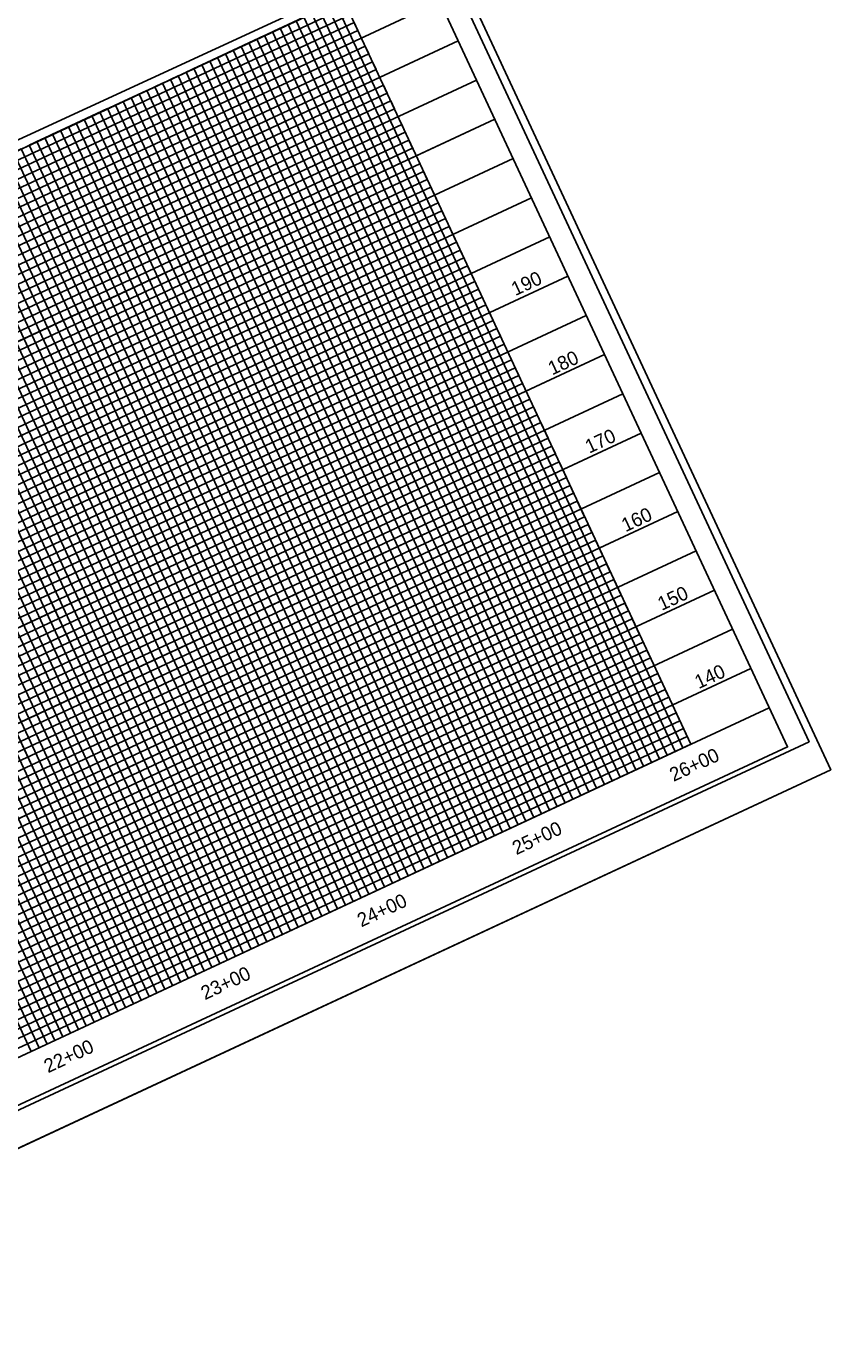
# Model space of a CAD drawing. Extents: x 2320593 to 2322597, y 921119 to 922832.
# Drawn here: x 2322132 to 2322597, y 921501 to 922260 of the extents above; entities that cross this region are included whole.
import ezdxf

# ---------------------------------------------------------------- set-up
doc = ezdxf.new("R2010")
doc.units = 0
for name, color, linetype in [('Default', 7, 'Continuous'), ('Sheet Cutting Line CELL', 7, 'Continuous'), ('Sheet DOT Grid CELL', 7, 'Continuous'), ('Sheet Layout Plan Border', 7, 'Continuous'), ('Sheet Layout Profile Border Port 2', 7, 'Continuous'), ('Sheet Plan And Profile CELL', 7, 'Continuous'), ('Sheet Plot Border Inside CELL', 7, 'Continuous'), ('Sheet Plot Border Outside CELL', 7, 'Continuous'), ('Sheet Profile Grid Major CELL', 7, 'Continuous'), ('Sheet Profile Grid Middle CELL', 7, 'Continuous'), ('Sheet Profile Grid Minor CELL', 7, 'Continuous')]:
    doc.layers.add(name, color=color, linetype=linetype)

msp = doc.modelspace()

# ---------------------------------------------------------------- linework, layer by layer
at = {"layer": 'Sheet Cutting Line CELL'}
msp.add_line((2321070.79, 921118.97), (2322596.67, 921830.22), dxfattribs=at)
at = {"layer": 'Sheet DOT Grid CELL'}
for p, q in [((2321000.96, 921662.89), (2322360.52, 922296.61)), ((2322315.2, 922275.49), (2322515.88, 921844.96)), ((2321022.08, 921617.57), (2322381.64, 922251.29)), ((2322269.88, 922254.36), (2322470.56, 921823.84)), ((2322224.56, 922233.24), (2322425.24, 921802.71)), ((2322179.24, 922212.12), (2322379.92, 921781.59)), ((2321043.21, 921572.25), (2322402.77, 922205.98)), ((2322133.92, 922190.99), (2322334.6, 921760.47)), ((2322088.61, 922169.87), (2322289.28, 921739.34)), ((2321064.33, 921526.94), (2322423.89, 922160.66)), ((2322043.29, 922148.74), (2322243.97, 921718.22)), ((2321997.97, 922127.62), (2322198.65, 921697.09)), ((2321085.46, 921481.62), (2322445.01, 922115.34)), ((2321952.65, 922106.5), (2322153.33, 921675.97)), ((2321106.58, 921436.3), (2322466.14, 922070.02)), ((2321127.7, 921390.98), (2322487.26, 922024.7)), ((2321148.83, 921345.66), (2322508.39, 921979.38)), ((2321169.95, 921300.34), (2322529.51, 921934.06)), ((2321191.08, 921255.02), (2322550.63, 921888.75))]:
    msp.add_line(p, q, dxfattribs=at)
at = {"layer": 'Sheet Layout Plan Border'}
msp.add_lwpolyline([(2322313.35, 922279.99), (2321040.83, 921692.7), (2320815.91, 922178.3), (2322085.86, 922766.57)], close=True, dxfattribs=at)
at = {"layer": 'Sheet Layout Profile Border Port 2'}
msp.add_lwpolyline([(2321046.28, 921684.02), (2322315.2, 922275.49), (2322515.88, 921844.96), (2321246.96, 921253.49)], close=True, dxfattribs=at)
at = {"layer": 'Sheet Plan And Profile CELL'}
msp.add_line((2322561.2, 921866.09), (2321201.64, 921232.36), dxfattribs=at)
msp.add_lwpolyline([(2322128.15, 922795.12), (2320768.59, 922161.4), (2321212.2, 921209.71), (2322571.76, 921843.43)], close=True, dxfattribs=at)
at = {"layer": 'Sheet Plot Border Inside CELL'}
msp.add_lwpolyline([(2321074.13, 921142.59), (2322584.14, 921846.44), (2322138.43, 922802.66), (2320628.41, 922098.81)], close=True, dxfattribs=at)
at = {"layer": 'Sheet Plot Border Outside CELL'}
msp.add_lwpolyline([(2321070.79, 921118.97), (2322596.67, 921830.22), (2322134.06, 922822.69), (2320608.18, 922111.45)], close=True, dxfattribs=at)
at = {"layer": 'Sheet Profile Grid Major CELL'}
for points in [[(2321000.96, 921662.89), (2322360.52, 922296.61)], [(2322515.88, 921844.96), (2322315.2, 922275.49)], [(2322381.64, 922251.29), (2321022.08, 921617.57), (2321043.21, 921572.25), (2322402.77, 922205.98)], [(2322425.24, 921802.71), (2322224.56, 922233.24), (2322269.88, 922254.36), (2322470.56, 921823.84)], [(2322334.6, 921760.47), (2322133.92, 922190.99), (2322179.24, 922212.12), (2322379.92, 921781.59)], [(2322243.97, 921718.22), (2322043.29, 922148.74), (2322088.61, 922169.87), (2322289.28, 921739.34)], [(2322423.89, 922160.66), (2321064.33, 921526.94), (2321085.46, 921481.62), (2322445.01, 922115.34)], [(2322153.33, 921675.97), (2321952.65, 922106.5), (2321997.97, 922127.62), (2322198.65, 921697.09)], [(2322466.14, 922070.02), (2321106.58, 921436.3), (2321127.7, 921390.98), (2322487.26, 922024.7)], [(2322508.39, 921979.38), (2321148.83, 921345.66), (2321169.95, 921300.34), (2322529.51, 921934.06)], [(2322550.63, 921888.75), (2321191.08, 921255.02)]]:
    msp.add_lwpolyline(points, dxfattribs=at)
at = {"layer": 'Sheet Profile Grid Middle CELL'}
for p, q in [((2321011.52, 921640.23), (2322371.08, 922273.95)), ((2322392.2, 922228.63), (2321032.65, 921594.91)), ((2321053.77, 921549.6), (2322413.33, 922183.32)), ((2322434.45, 922138), (2321074.89, 921504.28)), ((2321096.02, 921458.96), (2322455.58, 922092.68)), ((2322476.7, 922047.36), (2321117.14, 921413.64)), ((2321138.27, 921368.32), (2322497.82, 922002.04)), ((2322518.95, 921956.72), (2321159.39, 921323)), ((2321180.51, 921277.68), (2322540.07, 921911.4))]:
    msp.add_line(p, q, dxfattribs=at)
for points in [[(2322447.9, 921813.28), (2322247.22, 922243.8), (2322292.54, 922264.93), (2322493.22, 921834.4)], [(2322357.26, 921771.03), (2322156.58, 922201.55), (2322201.9, 922222.68), (2322402.58, 921792.15)], [(2322266.62, 921728.78), (2322065.95, 922159.31), (2322111.26, 922180.43), (2322311.94, 921749.9)], [(2322175.99, 921686.53), (2321975.31, 922117.06), (2322020.63, 922138.18), (2322221.31, 921707.66)]]:
    msp.add_lwpolyline(points, dxfattribs=at)
at = {"layer": 'Sheet Profile Grid Minor CELL'}
for points in [[(2321050.5, 921674.95), (2322319.42, 922266.42), (2322317.31, 922270.96), (2321048.39, 921679.48)], [(2322506.81, 921840.74), (2322306.13, 922271.26), (2322310.67, 922273.38), (2322511.35, 921842.85)], [(2322497.75, 921836.51), (2322297.07, 922267.04), (2322301.6, 922269.15), (2322502.28, 921838.62)], [(2321054.73, 921665.89), (2322323.65, 922257.36), (2322321.54, 922261.89), (2321052.62, 921670.42)], [(2322475.09, 921825.95), (2322274.41, 922256.48), (2322278.94, 922258.59), (2322479.62, 921828.06)], [(2322484.15, 921830.17), (2322283.48, 922260.7), (2322288.01, 922262.81), (2322488.69, 921832.29)], [(2321061.06, 921652.29), (2322329.99, 922243.77), (2322327.87, 922248.3), (2321058.95, 921656.82)], [(2322452.43, 921815.39), (2322251.75, 922245.91), (2322256.28, 922248.03), (2322456.96, 921817.5)], [(2322461.49, 921819.61), (2322260.82, 922250.14), (2322265.35, 922252.25), (2322466.03, 921821.73)], [(2322438.84, 921809.05), (2322238.16, 922239.58), (2322242.69, 922241.69), (2322443.37, 921811.16)], [(2321065.29, 921643.23), (2322334.21, 922234.7), (2322332.1, 922239.23), (2321063.18, 921647.76)], [(2322429.77, 921804.83), (2322229.09, 922235.35), (2322233.63, 922237.47), (2322434.3, 921806.94)], [(2321071.63, 921629.63), (2322340.55, 922221.11), (2322338.44, 922225.64), (2321069.51, 921634.17)], [(2322407.11, 921794.26), (2322206.43, 922224.79), (2322210.97, 922226.9), (2322411.64, 921796.38)], [(2322416.18, 921798.49), (2322215.5, 922229.02), (2322220.03, 922231.13), (2322420.71, 921800.6)], [(2322393.52, 921787.93), (2322192.84, 922218.45), (2322197.37, 922220.57), (2322398.05, 921790.04)], [(2321075.85, 921620.57), (2322344.77, 922212.04), (2322342.66, 922216.57), (2321073.74, 921625.1)], [(2322370.86, 921777.36), (2322170.18, 922207.89), (2322174.71, 922210), (2322375.39, 921779.48)], [(2322384.45, 921783.7), (2322183.77, 922214.23), (2322188.31, 922216.34), (2322388.98, 921785.81)], [(2321082.19, 921606.97), (2322351.11, 922198.45), (2322349, 922202.98), (2321080.08, 921611.51)], [(2322361.79, 921773.14), (2322161.12, 922203.67), (2322165.65, 922205.78), (2322366.33, 921775.25)], [(2322339.13, 921762.58), (2322138.46, 922193.1), (2322142.99, 922195.22), (2322343.67, 921764.69)], [(2322348.2, 921766.8), (2322147.52, 922197.33), (2322152.05, 922199.44), (2322352.73, 921768.92)], [(2321086.41, 921597.91), (2322355.33, 922189.38), (2322353.22, 922193.91), (2321084.3, 921602.44)], [(2322325.54, 921756.24), (2322124.86, 922186.77), (2322129.39, 922188.88), (2322330.07, 921758.35)], [(2321090.64, 921588.85), (2322359.56, 922180.32)], [(2322316.48, 921752.02), (2322115.8, 922182.54), (2322120.33, 922184.66), (2322321.01, 921754.13)], [(2321094.86, 921579.78), (2322363.78, 922171.26), (2322361.67, 922175.79), (2321092.75, 921584.31)], [(2322293.82, 921741.45), (2322093.14, 922171.98), (2322097.67, 922174.09), (2322298.35, 921743.57)], [(2322302.88, 921745.68), (2322102.2, 922176.21), (2322106.73, 922178.32), (2322307.41, 921747.79)], [(2321101.2, 921566.19), (2322370.12, 922157.66), (2322365.9, 922166.72), (2321096.98, 921575.25)], [(2322280.22, 921735.12), (2322079.54, 922165.64), (2322084.07, 922167.76), (2322284.75, 921737.23)], [(2322257.56, 921724.55), (2322056.88, 922155.08), (2322061.41, 922157.19), (2322262.09, 921726.67)], [(2322271.16, 921730.89), (2322070.48, 922161.42), (2322075.01, 922163.53), (2322275.69, 921733)], [(2321105.43, 921557.12), (2322374.35, 922148.6), (2322372.23, 922153.13), (2321103.31, 921561.66)], [(2322248.5, 921720.33), (2322047.82, 922150.86), (2322052.35, 922152.97), (2322253.03, 921722.44)], [(2321111.76, 921543.53), (2322380.68, 922135), (2322376.46, 922144.06), (2321107.54, 921552.59)], [(2322225.84, 921709.77), (2322025.16, 922140.29), (2322029.69, 922142.41), (2322230.37, 921711.88)], [(2322234.9, 921713.99), (2322034.22, 922144.52), (2322038.76, 922146.63), (2322239.43, 921716.11)], [(2322212.24, 921703.43), (2322011.56, 922133.96), (2322016.1, 922136.07), (2322216.77, 921705.54)], [(2321115.99, 921534.46), (2322384.91, 922125.94), (2322382.8, 922130.47), (2321113.87, 921539)], [(2322203.18, 921699.21), (2322002.5, 922129.73), (2322007.03, 922131.85), (2322207.71, 921701.32)], [(2321122.32, 921520.87), (2322391.25, 922112.34), (2322387.02, 922121.41), (2321118.1, 921529.93)], [(2322180.52, 921688.64), (2321979.84, 922119.17), (2321984.37, 922121.28), (2322185.05, 921690.76)], [(2322189.58, 921692.87), (2321988.9, 922123.4), (2321993.44, 922125.51), (2322194.11, 921694.98)], [(2322166.92, 921682.31), (2321966.25, 922112.83), (2321970.78, 922114.95), (2322171.46, 921684.42)], [(2321126.55, 921511.8), (2322395.47, 922103.28), (2322393.36, 922107.81), (2321124.44, 921516.34)], [(2322144.26, 921671.74), (2321943.59, 922102.27), (2321948.12, 922104.38), (2322148.8, 921673.86)], [(2322157.86, 921678.08), (2321957.18, 922108.61), (2321961.71, 922110.72), (2322162.39, 921680.19)], [(2321132.89, 921498.21), (2322401.81, 922089.68), (2322397.58, 922098.75), (2321128.66, 921507.27)], [(2322135.2, 921667.52), (2321934.52, 922098.05), (2321939.05, 922100.16), (2322139.73, 921669.63)], [(2321137.11, 921489.15), (2322406.03, 922080.62), (2322403.92, 922085.15), (2321135, 921493.68)], [(2321143.45, 921475.55), (2322412.37, 922067.02), (2322408.14, 922076.09), (2321139.22, 921484.61)], [(2321147.67, 921466.49), (2322416.59, 922057.96), (2322414.48, 922062.49), (2321145.56, 921471.02)], [(2321154.01, 921452.89), (2322422.93, 922044.36), (2322418.71, 922053.43), (2321149.79, 921461.95)], [(2321158.24, 921443.83), (2322427.16, 922035.3), (2322425.04, 922039.83), (2321156.12, 921448.36)], [(2321164.57, 921430.23), (2322433.49, 922021.7), (2322429.27, 922030.77), (2321160.35, 921439.3)], [(2321168.8, 921421.17), (2322437.72, 922012.64), (2322435.61, 922017.17), (2321166.68, 921425.7)], [(2321175.13, 921407.57), (2322444.06, 921999.04), (2322439.83, 922008.11), (2321170.91, 921416.64)], [(2321179.36, 921398.51), (2322448.28, 921989.98), (2322446.17, 921994.51), (2321177.25, 921403.04)], [(2321185.7, 921384.91), (2322454.62, 921976.39), (2322450.39, 921985.45), (2321181.47, 921393.98)], [(2321189.92, 921375.85), (2322458.84, 921967.32), (2322456.73, 921971.85), (2321187.81, 921380.38)], [(2321196.26, 921362.25), (2322465.18, 921953.73), (2322460.95, 921962.79), (2321192.03, 921371.32)], [(2321200.48, 921353.19), (2322469.4, 921944.66), (2322467.29, 921949.19), (2321198.37, 921357.72)], [(2321206.82, 921339.59), (2322475.74, 921931.07), (2322471.52, 921940.13), (2321202.6, 921348.66)], [(2321211.05, 921330.53), (2322479.97, 921922), (2322477.85, 921926.54), (2321208.93, 921335.06)], [(2321217.38, 921316.93), (2322486.3, 921908.41), (2322482.08, 921917.47), (2321213.16, 921326)], [(2321244.84, 921258.02), (2322513.76, 921849.49), (2322511.65, 921854.03), (2321242.73, 921262.55), (2321240.62, 921267.08), (2322509.54, 921858.56), (2322507.43, 921863.09), (2321238.51, 921271.62), (2321236.39, 921276.15), (2321234.28, 921280.68), (2322503.2, 921872.15), (2322501.09, 921876.68), (2321232.17, 921285.21), (2321230.06, 921289.74), (2322498.98, 921881.22), (2322496.87, 921885.75), (2321227.94, 921294.28), (2321225.83, 921298.81), (2321223.72, 921303.34), (2322492.64, 921894.81), (2322490.53, 921899.34), (2321221.61, 921307.87), (2321219.49, 921312.4), (2322488.42, 921903.88)]]:
    msp.add_lwpolyline(points, dxfattribs=at)

# ---------------------------------------------------------------- texts
at = {"layer": 'Default'}
for s, p in [('190', (2322414.63, 922103.81)), ('180', (2322435.86, 922057.96)), ('170', (2322457.27, 922012.78)), ('160', (2322478.22, 921967.38)), ('150', (2322499.12, 921921.95)), ('140', (2322520.47, 921876.74)), ('26+00', (2322505.96, 921823.18)), ('25+00', (2322415.17, 921780.86)), ('24+00', (2322325.68, 921739.15)), ('23+00', (2322235.44, 921697.09)), ('22+00', (2322144.86, 921654.87))]:
    msp.add_text(s, height=8, rotation=24.9913, dxfattribs=at).set_placement(p)

doc.saveas('drawing.dxf')
